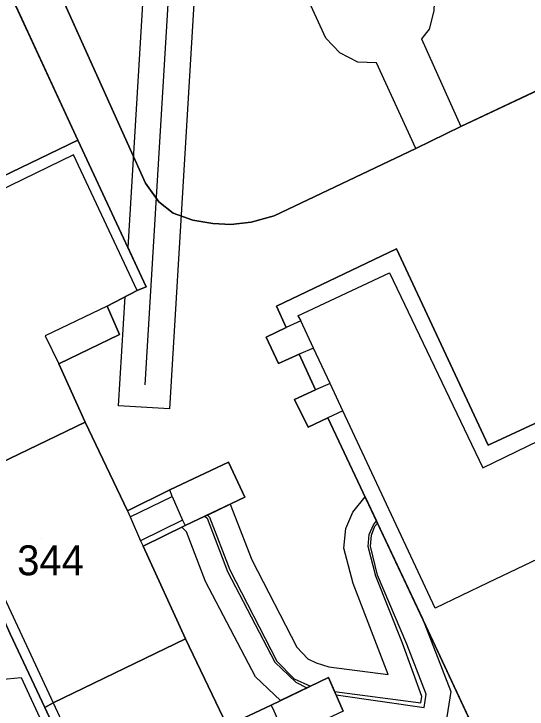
# Model space of a CAD drawing. Extents: x -264070 to -262271, y -1238894 to -1238141.
# Drawn here: x -263717.91 to -263683.57, y -1238689.65 to -1238643.13 of the extents above; entities that cross this region are included whole.
import ezdxf

# ---------------------------------------------------------------- set-up
doc = ezdxf.new("R2010")
doc.units = 0
for name, color, linetype in [('body_kn', 7, 'Continuous'), ('kladpar_druhypozemkov', 7, 'Continuous'), ('kladpar_hranice', 7, 'Continuous'), ('kladpar_parcelnecisla', 7, 'Continuous'), ('kladpar_plochy', 7, 'Continuous'), ('tarchy_linie', 7, 'Continuous'), ('zappar_hrandruhpozemk', 7, 'Continuous')]:
    doc.layers.add(name, color=color, linetype=linetype)

msp = doc.modelspace()

# ---------------------------------------------------------------- linework, layer by layer
at = {"layer": 'body_kn'}
for p, q in [((-263690.12, -1238644.15), (-263690.12, -1238644.15)), ((-263697.04, -1238644.76), (-263697.04, -1238644.76)), ((-263690.65, -1238644.81), (-263690.65, -1238644.81)), ((-263696.11, -1238645.74), (-263696.11, -1238645.74)), ((-263694.91, -1238646.36), (-263694.91, -1238646.36)), ((-263693.66, -1238646.41), (-263693.66, -1238646.41)), ((-263688, -1238650.67), (-263688, -1238650.67)), ((-263688, -1238650.67), (-263688, -1238650.67)), ((-263713.63, -1238651.59), (-263713.63, -1238651.59)), ((-263713.63, -1238651.59), (-263713.63, -1238651.59)), ((-263691.02, -1238652.14), (-263691.02, -1238652.14)), ((-263691.02, -1238652.14), (-263691.02, -1238652.14)), ((-263713.93, -1238652.57), (-263713.93, -1238652.57)), ((-263709.11, -1238654.46), (-263709.11, -1238654.46)), ((-263708.21, -1238655.7), (-263708.21, -1238655.7)), ((-263707.26, -1238656.46), (-263707.26, -1238656.46)), ((-263705.94, -1238656.94), (-263705.94, -1238656.94)), ((-263702.04, -1238657.07), (-263702.04, -1238657.07)), ((-263700.49, -1238656.65), (-263700.49, -1238656.65)), ((-263704.61, -1238657.16), (-263704.61, -1238657.16)), ((-263703.39, -1238657.22), (-263703.39, -1238657.22)), ((-263710.27, -1238658.77), (-263710.27, -1238658.77)), ((-263692.32, -1238658.86), (-263692.32, -1238658.86)), ((-263692.77, -1238660.46), (-263692.77, -1238660.46)), ((-263709.67, -1238661.64), (-263709.67, -1238661.64)), ((-263709.67, -1238661.64), (-263709.67, -1238661.64)), ((-263709.05, -1238661.39), (-263709.05, -1238661.39)), ((-263710.47, -1238662.05), (-263710.47, -1238662.05)), ((-263711.68, -1238662.68), (-263711.68, -1238662.68)), ((-263711.68, -1238662.68), (-263711.68, -1238662.68)), ((-263700.34, -1238662.68), (-263700.34, -1238662.68)), ((-263698.91, -1238663.34), (-263698.91, -1238663.34)), ((-263698.71, -1238663.68), (-263698.71, -1238663.68)), ((-263698.71, -1238663.68), (-263698.71, -1238663.68)), ((-263699.69, -1238664.12), (-263699.69, -1238664.12)), ((-263715.81, -1238664.67), (-263715.81, -1238664.67)), ((-263710.85, -1238664.59), (-263710.85, -1238664.59)), ((-263701.03, -1238664.76), (-263701.03, -1238664.76)), ((-263698.82, -1238665.91), (-263698.82, -1238665.91)), ((-263697.86, -1238665.5), (-263697.86, -1238665.5)), ((-263714.91, -1238666.54), (-263714.91, -1238666.54)), ((-263700.2, -1238666.52), (-263700.2, -1238666.52)), ((-263709.12, -1238667.95), (-263709.12, -1238667.95)), ((-263696.75, -1238667.86), (-263696.75, -1238667.86)), ((-263697.73, -1238668.28), (-263697.73, -1238668.28)), ((-263699.14, -1238668.94), (-263699.14, -1238668.94)), ((-263710.91, -1238669.35), (-263710.91, -1238669.35)), ((-263707.51, -1238669.55), (-263707.51, -1238669.55)), ((-263695.9, -1238669.7), (-263695.9, -1238669.7)), ((-263713.14, -1238670.44), (-263713.14, -1238670.44)), ((-263713.14, -1238670.44), (-263713.14, -1238670.44)), ((-263696.9, -1238670.15), (-263696.9, -1238670.15)), ((-263698.23, -1238670.78), (-263698.23, -1238670.78)), ((-263686.17, -1238671.99), (-263686.17, -1238671.99)), ((-263703.55, -1238673.13), (-263703.55, -1238673.13)), ((-263686.53, -1238673.5), (-263686.53, -1238673.5)), ((-263707.48, -1238674.97), (-263707.48, -1238674.97)), ((-263707.32, -1238675.42), (-263707.32, -1238675.42)), ((-263702.45, -1238675.47), (-263702.45, -1238675.47)), ((-263694.4, -1238675.45), (-263694.4, -1238675.45)), ((-263703.44, -1238675.94), (-263703.44, -1238675.94)), ((-263703.44, -1238675.94), (-263703.44, -1238675.94)), ((-263710.31, -1238676.39), (-263710.31, -1238676.39)), ((-263710.31, -1238676.39), (-263710.31, -1238676.39)), ((-263695.23, -1238676.48), (-263695.23, -1238676.48)), ((-263710.13, -1238676.79), (-263710.13, -1238676.79)), ((-263706.62, -1238677), (-263706.62, -1238677)), ((-263705.13, -1238676.74), (-263705.13, -1238676.74)), ((-263705.13, -1238676.74), (-263705.13, -1238676.74)), ((-263704.99, -1238676.88), (-263704.99, -1238676.88)), ((-263704.96, -1238676.66), (-263704.96, -1238676.66)), ((-263704.96, -1238676.66), (-263704.96, -1238676.66)), ((-263704.82, -1238676.81), (-263704.82, -1238676.81)), ((-263693.65, -1238677.06), (-263693.65, -1238677.06)), ((-263706.67, -1238677.47), (-263706.67, -1238677.47)), ((-263706.46, -1238677.37), (-263706.46, -1238677.37)), ((-263695.7, -1238677.57), (-263695.7, -1238677.57)), ((-263693.85, -1238677.31), (-263693.85, -1238677.31)), ((-263693.76, -1238677.41), (-263693.76, -1238677.41)), ((-263693.58, -1238677.2), (-263693.58, -1238677.2)), ((-263706.36, -1238677.78), (-263706.36, -1238677.78)), ((-263694.13, -1238677.97), (-263694.13, -1238677.97)), ((-263693.99, -1238678), (-263693.99, -1238678)), ((-263709.45, -1238678.38), (-263709.45, -1238678.38)), ((-263709.45, -1238678.38), (-263709.45, -1238678.38)), ((-263709.26, -1238678.75), (-263709.26, -1238678.75)), ((-263695.83, -1238678.88), (-263695.83, -1238678.88)), ((-263694.21, -1238678.76), (-263694.21, -1238678.76)), ((-263694.05, -1238678.74), (-263694.05, -1238678.74)), ((-263702, -1238679.66), (-263702, -1238679.66)), ((-263703.46, -1238680.32), (-263703.46, -1238680.32)), ((-263703.62, -1238680.45), (-263703.62, -1238680.45)), ((-263693.7, -1238680.75), (-263693.7, -1238680.75)), ((-263693.58, -1238680.68), (-263693.58, -1238680.68)), ((-263705.08, -1238681.11), (-263705.08, -1238681.11)), ((-263695.22, -1238681.25), (-263695.22, -1238681.25)), ((-263686.19, -1238681.2), (-263686.19, -1238681.2)), ((-263689.73, -1238682.9), (-263689.73, -1238682.9)), ((-263690.57, -1238683.59), (-263690.57, -1238683.59)), ((-263690.34, -1238684.08), (-263690.34, -1238684.08)), ((-263706.42, -1238684.94), (-263706.42, -1238684.94)), ((-263706.42, -1238684.94), (-263706.42, -1238684.94)), ((-263691.92, -1238685.24), (-263691.92, -1238685.24)), ((-263691.62, -1238685.31), (-263691.62, -1238685.31)), ((-263698.99, -1238685.5), (-263698.99, -1238685.5)), ((-263698.25, -1238686.29), (-263698.25, -1238686.29)), ((-263700.45, -1238686.5), (-263700.45, -1238686.5)), ((-263700.31, -1238686.43), (-263700.31, -1238686.43)), ((-263697.68, -1238686.56), (-263697.68, -1238686.56)), ((-263696.84, -1238686.81), (-263696.84, -1238686.81)), ((-263692.86, -1238687.33), (-263692.86, -1238687.33)), ((-263717.42, -1238687.53), (-263717.42, -1238687.53)), ((-263717.42, -1238687.53), (-263717.42, -1238687.53)), ((-263701.75, -1238687.48), (-263701.75, -1238687.48)), ((-263699.16, -1238687.63), (-263699.16, -1238687.63)), ((-263696.86, -1238687.54), (-263696.86, -1238687.54)), ((-263699.05, -1238687.84), (-263699.05, -1238687.84)), ((-263698.31, -1238688.23), (-263698.31, -1238688.23)), ((-263698.07, -1238688.12), (-263698.07, -1238688.12)), ((-263696.45, -1238688.47), (-263696.45, -1238688.47)), ((-263696.45, -1238688.47), (-263696.45, -1238688.47)), ((-263696.35, -1238688.7), (-263696.35, -1238688.7)), ((-263696.35, -1238688.7), (-263696.35, -1238688.7)), ((-263690.33, -1238688.64), (-263690.33, -1238688.64)), ((-263688.68, -1238688.46), (-263688.68, -1238688.46)), ((-263700.07, -1238689.08), (-263700.07, -1238689.08)), ((-263690.62, -1238688.81), (-263690.62, -1238688.81)), ((-263715.84, -1238689.53), (-263715.84, -1238689.53)), ((-263715.28, -1238689.23), (-263715.28, -1238689.23)), ((-263715.28, -1238689.23), (-263715.28, -1238689.23)), ((-263700.7, -1238689.38), (-263700.7, -1238689.38)), ((-263700.7, -1238689.38), (-263700.7, -1238689.38)), ((-263690.68, -1238689.22), (-263690.68, -1238689.22)), ((-263690.47, -1238689.53), (-263690.47, -1238689.53))]:
    msp.add_line(p, q, dxfattribs=at)
at = {"layer": 'kladpar_druhypozemkov'}
msp.add_line((-263716.09, -1238678.26), (-263716.09, -1238678.26), dxfattribs=at)
at = {"layer": 'kladpar_hranice'}
msp.add_line((-263691.02, -1238652.14), (-263688, -1238650.67), dxfattribs=at)
for points in [[(-263678.79, -1238646.32), (-263688, -1238650.67), (-263691.02, -1238652.14), (-263700.49, -1238656.65), (-263702.04, -1238657.07), (-263703.39, -1238657.22), (-263704.61, -1238657.16), (-263705.94, -1238656.94), (-263707.26, -1238656.46), (-263708.21, -1238655.7), (-263709.11, -1238654.46), (-263717.15, -1238636.58), (-263717.43, -1238635.75), (-263717.63, -1238634.35), (-263717.66, -1238632.56), (-263717.22, -1238631.02), (-263716.5, -1238629.74), (-263715.64, -1238628.72), (-263692.98, -1238617.98)], [(-263727.01, -1238634.34), (-263725.3, -1238634.2), (-263723.65, -1238634.44), (-263722.48, -1238634.91), (-263721.65, -1238635.58), (-263720.87, -1238636.45), (-263720.28, -1238637.36), (-263719.81, -1238638.22), (-263713.63, -1238651.59), (-263722.58, -1238655.89), (-263722.27, -1238656.62), (-263724.24, -1238657.49), (-263724.49, -1238656.84), (-263729.95, -1238659.53), (-263722.61, -1238674.95), (-263719.38, -1238681.88), (-263718.16, -1238684.61), (-263715.84, -1238689.53), (-263712.45, -1238696.86)], [(-263717.15, -1238636.58), (-263709.11, -1238654.46), (-263708.21, -1238655.7), (-263707.26, -1238656.46), (-263705.94, -1238656.94), (-263704.61, -1238657.16), (-263703.39, -1238657.22), (-263702.04, -1238657.07), (-263700.49, -1238656.65), (-263691.02, -1238652.14)], [(-263695.87, -1238689.79), (-263696.86, -1238687.54), (-263700.7, -1238689.38), (-263703.64, -1238690.77), (-263706.42, -1238684.94), (-263709.26, -1238678.75), (-263706.46, -1238677.37), (-263702.45, -1238675.47), (-263703.55, -1238673.13), (-263707.48, -1238674.97), (-263710.31, -1238676.39), (-263713.14, -1238670.44), (-263714.91, -1238666.54), (-263710.85, -1238664.59), (-263711.68, -1238662.68), (-263709.67, -1238661.64), (-263709.05, -1238661.39), (-263713.63, -1238651.59), (-263719.81, -1238638.22)], [(-263688, -1238650.67), (-263678.79, -1238646.32)], [(-263713.63, -1238651.59), (-263709.05, -1238661.39), (-263709.67, -1238661.64), (-263711.68, -1238662.68), (-263710.85, -1238664.59), (-263714.91, -1238666.54), (-263713.14, -1238670.44), (-263722.05, -1238674.72), (-263722.61, -1238674.95), (-263729.95, -1238659.53), (-263724.49, -1238656.84), (-263724.24, -1238657.49), (-263722.27, -1238656.62), (-263722.58, -1238655.89), (-263713.63, -1238651.59)], [(-263682.81, -1238670.42), (-263686.17, -1238671.99), (-263692.32, -1238658.86), (-263700.34, -1238662.68), (-263699.69, -1238664.12), (-263701.03, -1238664.76), (-263700.2, -1238666.52), (-263698.82, -1238665.91), (-263697.73, -1238668.28), (-263699.14, -1238668.94), (-263698.23, -1238670.78), (-263696.9, -1238670.15), (-263690.34, -1238684.08), (-263675.44, -1238716)], [(-263650.18, -1238703.94), (-263675.44, -1238716), (-263690.34, -1238684.08), (-263696.9, -1238670.15), (-263698.23, -1238670.78), (-263699.14, -1238668.94), (-263697.73, -1238668.28), (-263698.82, -1238665.91), (-263700.2, -1238666.52), (-263701.03, -1238664.76), (-263699.69, -1238664.12), (-263700.34, -1238662.68), (-263692.32, -1238658.86), (-263686.17, -1238671.99), (-263682.81, -1238670.42), (-263682.99, -1238670.07), (-263679.88, -1238668.48), (-263679.68, -1238668.92), (-263676.39, -1238667.38)], [(-263713.14, -1238670.44), (-263710.31, -1238676.39), (-263707.48, -1238674.97), (-263703.55, -1238673.13), (-263702.45, -1238675.47), (-263706.46, -1238677.37), (-263709.26, -1238678.75), (-263706.42, -1238684.94), (-263715.28, -1238689.23), (-263715.84, -1238689.53), (-263718.16, -1238684.61), (-263719.38, -1238681.88), (-263722.61, -1238674.95), (-263722.05, -1238674.72), (-263713.14, -1238670.44)], [(-263706.42, -1238684.94), (-263703.64, -1238690.77), (-263700.7, -1238689.38), (-263696.86, -1238687.54), (-263695.87, -1238689.79), (-263699.74, -1238691.59), (-263702.61, -1238693), (-263699.76, -1238699.32), (-263708.49, -1238703.65), (-263709.03, -1238703.95), (-263711.13, -1238699.49), (-263712.45, -1238696.86), (-263715.84, -1238689.53), (-263715.28, -1238689.23), (-263706.42, -1238684.94)]]:
    msp.add_lwpolyline(points, dxfattribs=at)
at = {"layer": 'kladpar_plochy'}
for p, q in [((-263717.15, -1238636.58), (-263709.11, -1238654.46)), ((-263713.63, -1238651.59), (-263719.81, -1238638.22)), ((-263688, -1238650.67), (-263678.79, -1238646.32)), ((-263691.02, -1238652.14), (-263688, -1238650.67)), ((-263709.05, -1238661.39), (-263713.63, -1238651.59)), ((-263700.49, -1238656.65), (-263691.02, -1238652.14)), ((-263709.11, -1238654.46), (-263708.21, -1238655.7)), ((-263708.21, -1238655.7), (-263707.26, -1238656.46)), ((-263707.26, -1238656.46), (-263705.94, -1238656.94)), ((-263705.94, -1238656.94), (-263704.61, -1238657.16)), ((-263703.39, -1238657.22), (-263702.04, -1238657.07)), ((-263702.04, -1238657.07), (-263700.49, -1238656.65)), ((-263704.61, -1238657.16), (-263703.39, -1238657.22)), ((-263692.32, -1238658.86), (-263700.34, -1238662.68)), ((-263700.34, -1238662.68), (-263692.32, -1238658.86)), ((-263686.17, -1238671.99), (-263692.32, -1238658.86)), ((-263692.32, -1238658.86), (-263686.17, -1238671.99)), ((-263711.68, -1238662.68), (-263709.67, -1238661.64)), ((-263709.67, -1238661.64), (-263709.05, -1238661.39)), ((-263710.85, -1238664.59), (-263711.68, -1238662.68)), ((-263700.34, -1238662.68), (-263699.69, -1238664.12)), ((-263699.69, -1238664.12), (-263700.34, -1238662.68)), ((-263699.69, -1238664.12), (-263701.03, -1238664.76)), ((-263701.03, -1238664.76), (-263699.69, -1238664.12)), ((-263714.91, -1238666.54), (-263710.85, -1238664.59)), ((-263701.03, -1238664.76), (-263700.2, -1238666.52)), ((-263700.2, -1238666.52), (-263701.03, -1238664.76)), ((-263700.2, -1238666.52), (-263698.82, -1238665.91)), ((-263698.82, -1238665.91), (-263700.2, -1238666.52)), ((-263698.82, -1238665.91), (-263697.73, -1238668.28)), ((-263697.73, -1238668.28), (-263698.82, -1238665.91)), ((-263713.14, -1238670.44), (-263714.91, -1238666.54)), ((-263697.73, -1238668.28), (-263699.14, -1238668.94)), ((-263699.14, -1238668.94), (-263697.73, -1238668.28)), ((-263699.14, -1238668.94), (-263698.23, -1238670.78)), ((-263698.23, -1238670.78), (-263699.14, -1238668.94)), ((-263710.31, -1238676.39), (-263713.14, -1238670.44)), ((-263698.23, -1238670.78), (-263696.9, -1238670.15)), ((-263696.9, -1238670.15), (-263698.23, -1238670.78)), ((-263696.9, -1238670.15), (-263690.34, -1238684.08)), ((-263690.34, -1238684.08), (-263696.9, -1238670.15)), ((-263682.81, -1238670.42), (-263686.17, -1238671.99)), ((-263686.17, -1238671.99), (-263682.81, -1238670.42)), ((-263703.55, -1238673.13), (-263707.48, -1238674.97)), ((-263702.45, -1238675.47), (-263703.55, -1238673.13)), ((-263707.48, -1238674.97), (-263710.31, -1238676.39)), ((-263706.46, -1238677.37), (-263702.45, -1238675.47)), ((-263709.26, -1238678.75), (-263706.46, -1238677.37)), ((-263706.42, -1238684.94), (-263709.26, -1238678.75)), ((-263690.34, -1238684.08), (-263675.44, -1238716)), ((-263675.44, -1238716), (-263690.34, -1238684.08)), ((-263703.64, -1238690.77), (-263706.42, -1238684.94)), ((-263696.86, -1238687.54), (-263700.7, -1238689.38)), ((-263695.87, -1238689.79), (-263696.86, -1238687.54)), ((-263700.7, -1238689.38), (-263703.64, -1238690.77))]:
    msp.add_line(p, q, dxfattribs=at)
for points in [[(-263678.79, -1238646.32), (-263688, -1238650.67), (-263691.02, -1238652.14), (-263700.49, -1238656.65), (-263702.04, -1238657.07), (-263703.39, -1238657.22), (-263704.61, -1238657.16), (-263705.94, -1238656.94), (-263707.26, -1238656.46), (-263708.21, -1238655.7), (-263709.11, -1238654.46), (-263717.15, -1238636.58)], [(-263719.81, -1238638.22), (-263713.63, -1238651.59), (-263722.58, -1238655.89), (-263722.27, -1238656.62), (-263724.24, -1238657.49), (-263724.49, -1238656.84), (-263729.95, -1238659.53), (-263722.61, -1238674.95), (-263719.38, -1238681.88), (-263718.16, -1238684.61), (-263715.84, -1238689.53), (-263712.45, -1238696.86)]]:
    msp.add_lwpolyline(points, dxfattribs=at)
for points in [[(-263713.63, -1238651.59), (-263709.05, -1238661.39), (-263709.67, -1238661.64), (-263711.68, -1238662.68), (-263710.85, -1238664.59), (-263714.91, -1238666.54), (-263713.14, -1238670.44), (-263722.05, -1238674.72), (-263722.61, -1238674.95), (-263729.95, -1238659.53), (-263724.49, -1238656.84), (-263724.24, -1238657.49), (-263722.27, -1238656.62), (-263722.58, -1238655.89)], [(-263713.14, -1238670.44), (-263710.31, -1238676.39), (-263707.48, -1238674.97), (-263703.55, -1238673.13), (-263702.45, -1238675.47), (-263706.46, -1238677.37), (-263709.26, -1238678.75), (-263706.42, -1238684.94), (-263715.28, -1238689.23), (-263715.84, -1238689.53), (-263718.16, -1238684.61), (-263719.38, -1238681.88), (-263722.61, -1238674.95), (-263722.05, -1238674.72)], [(-263706.42, -1238684.94), (-263703.64, -1238690.77), (-263700.7, -1238689.38), (-263696.86, -1238687.54), (-263695.87, -1238689.79), (-263699.74, -1238691.59), (-263702.61, -1238693), (-263699.76, -1238699.32), (-263708.49, -1238703.65), (-263709.03, -1238703.95), (-263711.13, -1238699.49), (-263712.45, -1238696.86), (-263715.84, -1238689.53), (-263715.28, -1238689.23)]]:
    msp.add_lwpolyline(points, close=True, dxfattribs=at)
at = {"layer": 'tarchy_linie'}
for points in [[(-263709.12, -1238667.95), (-263707.52, -1238641.35), (-263681.4, -1238629.12), (-263661.53, -1238620.2), (-263640.3, -1238637.56), (-263618.59, -1238683.83), (-263593.48, -1238736.77), (-263576.63, -1238729.18), (-263561.94, -1238722.36)], [(-263680.69, -1238630.67), (-263705.88, -1238642.46), (-263707.51, -1238669.55), (-263710.91, -1238669.35), (-263710.47, -1238662.05), (-263709.67, -1238661.64), (-263709.05, -1238661.39), (-263710.27, -1238658.77), (-263709.16, -1238640.24), (-263682.11, -1238627.57)], [(-263703.44, -1238675.94), (-263702, -1238679.66), (-263698.99, -1238685.5), (-263698.25, -1238686.29), (-263697.68, -1238686.56), (-263696.84, -1238686.81), (-263692.86, -1238687.33), (-263695.22, -1238681.25), (-263695.83, -1238678.88), (-263695.7, -1238677.57), (-263695.23, -1238676.48), (-263694.4, -1238675.45), (-263693.65, -1238677.06), (-263693.58, -1238677.2), (-263690.57, -1238683.59), (-263688.68, -1238688.46), (-263689.15, -1238691.43)], [(-263695.87, -1238689.79), (-263696.35, -1238688.7), (-263696.45, -1238688.47), (-263696.86, -1238687.54), (-263698.07, -1238688.12), (-263698.31, -1238688.23), (-263700.07, -1238689.08), (-263701.75, -1238687.48), (-263705.08, -1238681.11), (-263706.36, -1238677.78), (-263706.67, -1238677.47), (-263706.46, -1238677.37), (-263705.13, -1238676.74), (-263704.96, -1238676.66), (-263703.44, -1238675.94)], [(-263705.13, -1238676.74), (-263704.99, -1238676.88), (-263703.62, -1238680.45), (-263700.45, -1238686.5), (-263699.05, -1238687.84), (-263698.31, -1238688.23)], [(-263704.96, -1238676.66), (-263704.82, -1238676.81), (-263703.46, -1238680.32), (-263700.31, -1238686.43), (-263699.16, -1238687.63), (-263698.07, -1238688.12)], [(-263696.45, -1238688.47), (-263690.68, -1238689.22), (-263690.62, -1238688.81), (-263691.92, -1238685.24), (-263693.7, -1238680.75), (-263694.21, -1238678.76), (-263694.13, -1238677.97), (-263693.85, -1238677.31), (-263693.65, -1238677.06)], [(-263696.35, -1238688.7), (-263690.47, -1238689.53), (-263690.33, -1238688.64), (-263691.62, -1238685.31), (-263693.58, -1238680.68), (-263694.05, -1238678.74), (-263693.99, -1238678), (-263693.76, -1238677.41), (-263693.58, -1238677.2)]]:
    msp.add_lwpolyline(points, dxfattribs=at)
at = {"layer": 'zappar_hrandruhpozemk'}
for p, q in [((-263697.04, -1238644.76), (-263699.73, -1238638.89)), ((-263713.93, -1238652.57), (-263722.27, -1238656.62)), ((-263709.67, -1238661.64), (-263713.93, -1238652.57)), ((-263711.68, -1238662.68), (-263715.81, -1238664.67)), ((-263698.91, -1238663.34), (-263698.71, -1238663.68)), ((-263698.71, -1238663.68), (-263699.69, -1238664.12)), ((-263697.86, -1238665.5), (-263698.71, -1238663.68)), ((-263715.81, -1238664.67), (-263714.91, -1238666.54)), ((-263697.86, -1238665.5), (-263698.82, -1238665.91)), ((-263696.75, -1238667.86), (-263697.86, -1238665.5)), ((-263696.75, -1238667.86), (-263697.73, -1238668.28)), ((-263695.9, -1238669.7), (-263696.75, -1238667.86)), ((-263695.9, -1238669.7), (-263696.9, -1238670.15)), ((-263689.73, -1238682.9), (-263695.9, -1238669.7)), ((-263722.05, -1238674.72), (-263715.28, -1238689.23)), ((-263707.32, -1238675.42), (-263707.48, -1238674.97)), ((-263710.13, -1238676.79), (-263707.32, -1238675.42)), ((-263707.32, -1238675.42), (-263706.62, -1238677)), ((-263710.31, -1238676.39), (-263710.13, -1238676.79)), ((-263710.13, -1238676.79), (-263709.45, -1238678.38)), ((-263706.62, -1238677), (-263709.45, -1238678.38)), ((-263706.62, -1238677), (-263706.46, -1238677.37)), ((-263709.45, -1238678.38), (-263709.26, -1238678.75)), ((-263686.19, -1238681.2), (-263689.73, -1238682.9)), ((-263717.42, -1238687.53), (-263714.21, -1238694.52)), ((-263715.28, -1238689.23), (-263708.49, -1238703.65))]:
    msp.add_line(p, q, dxfattribs=at)
for points in [[(-263689.75, -1238641.38), (-263689.81, -1238642.94), (-263690.12, -1238644.15), (-263690.65, -1238644.81), (-263688, -1238650.67)], [(-263691.02, -1238652.14), (-263693.66, -1238646.41), (-263694.91, -1238646.36), (-263696.11, -1238645.74), (-263697.04, -1238644.76)], [(-263698.91, -1238663.34), (-263692.77, -1238660.46), (-263686.53, -1238673.5), (-263682.03, -1238671.32)], [(-263676.6, -1238676.68), (-263678.53, -1238677.55), (-263686.19, -1238681.2)], [(-263721.3, -1238686.09), (-263720.7, -1238686.87), (-263719.89, -1238687.34), (-263718.82, -1238687.66), (-263717.42, -1238687.53)], [(-263700.7, -1238689.38), (-263700.52, -1238689.76), (-263699.93, -1238691.08), (-263699.74, -1238691.59)]]:
    msp.add_lwpolyline(points, dxfattribs=at)

# ---------------------------------------------------------------- texts
at = {"layer": 'kladpar_parcelnecisla'}
msp.add_text('344', height=2, dxfattribs=at).set_placement((-263717.691, -1238680.69))

doc.saveas('drawing.dxf')
